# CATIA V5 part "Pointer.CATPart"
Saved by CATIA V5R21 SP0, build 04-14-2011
Part number: Part1
Bounding box of the stored display mesh (mm): x -12.875 to 12.875, y -12.732 to 12.732, z 0 to 100
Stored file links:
  D:\CATIA V5R21 E-RESOURCES\CATIA-V5R21\catia-v5r21-prt\c16-catia-v5r20-prt\Point Curve Joint-(16-36)\CAT_V5R21_Pointer.CATPart
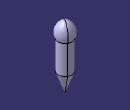
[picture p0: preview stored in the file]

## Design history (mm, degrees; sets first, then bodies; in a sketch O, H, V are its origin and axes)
Body1 (main body)
  Sketch1 on yz-plane, origin (0, 0, 0), H (0, 1, 0), V (0, 0, 1)
    line L1 (0, 0) -> (10.9446, 30.0702)
    point P1 (10.9446, 30.0702)
    line L2 (10.9446, 30.0702) -> (10.9446, 75.0702)
    point P2 (10.9446, 30.0702)
    point P3 (10.9446, 75.0702)
    arc A1 centre (-4.3336, 83.2301) radius 17.3208 from (10.9446, 75.0702) to (0, 100) ccw
    point P5 (0, 100)
    point P6 (10.9446, 91.3901)
    line L3 (0, 0) -> (0, 100)
    reference intersected line E1 through (0, 0) direction (-1, 0) from xy-plane
    reference intersected line E3 through (0, 0) direction (0, 1) from zx-plane
    radius A1 = 17.3208
    angle L1 L3 = 20
    distance O P1 = 32
    distance O P5 = 100
    distance P2 P3 = 45
    coincidence: P2 L1, P5 V, A1 P6, P6 L2, P2 P1, E3 P5, P1 L2
    vertical: L2 V, L3 V, E3 V
    horizontal: E1 H
    perpendicularity: E1 L2
  Shaft1: profile Sketch1, axis Sketch1.L3, angle 360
